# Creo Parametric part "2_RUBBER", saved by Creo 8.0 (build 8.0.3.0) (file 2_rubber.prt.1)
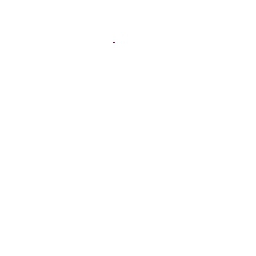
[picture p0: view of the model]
Units: millimeter Newton Second (mmNs); MM, TONNE, SECS

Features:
  1. datum plane "DTM1"
  2. datum plane "DTM2"
  3. datum plane "DTM3"
  4. coordinate system
  5. datum plane "DTM4"
  6. datum plane "DTM5"
  7. protrusion
  8. cut

Other named items: CS0

Layers: 0_ALL_AXIS, 0_ALL_CSYS, 0_ALL_CURVES, 0_ALL_PLANES, 0_ALL_POINTS, 0_ALL_SURFS, RUBBER

Surfaces: 4 plane, 4 torus, 3 cylinder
